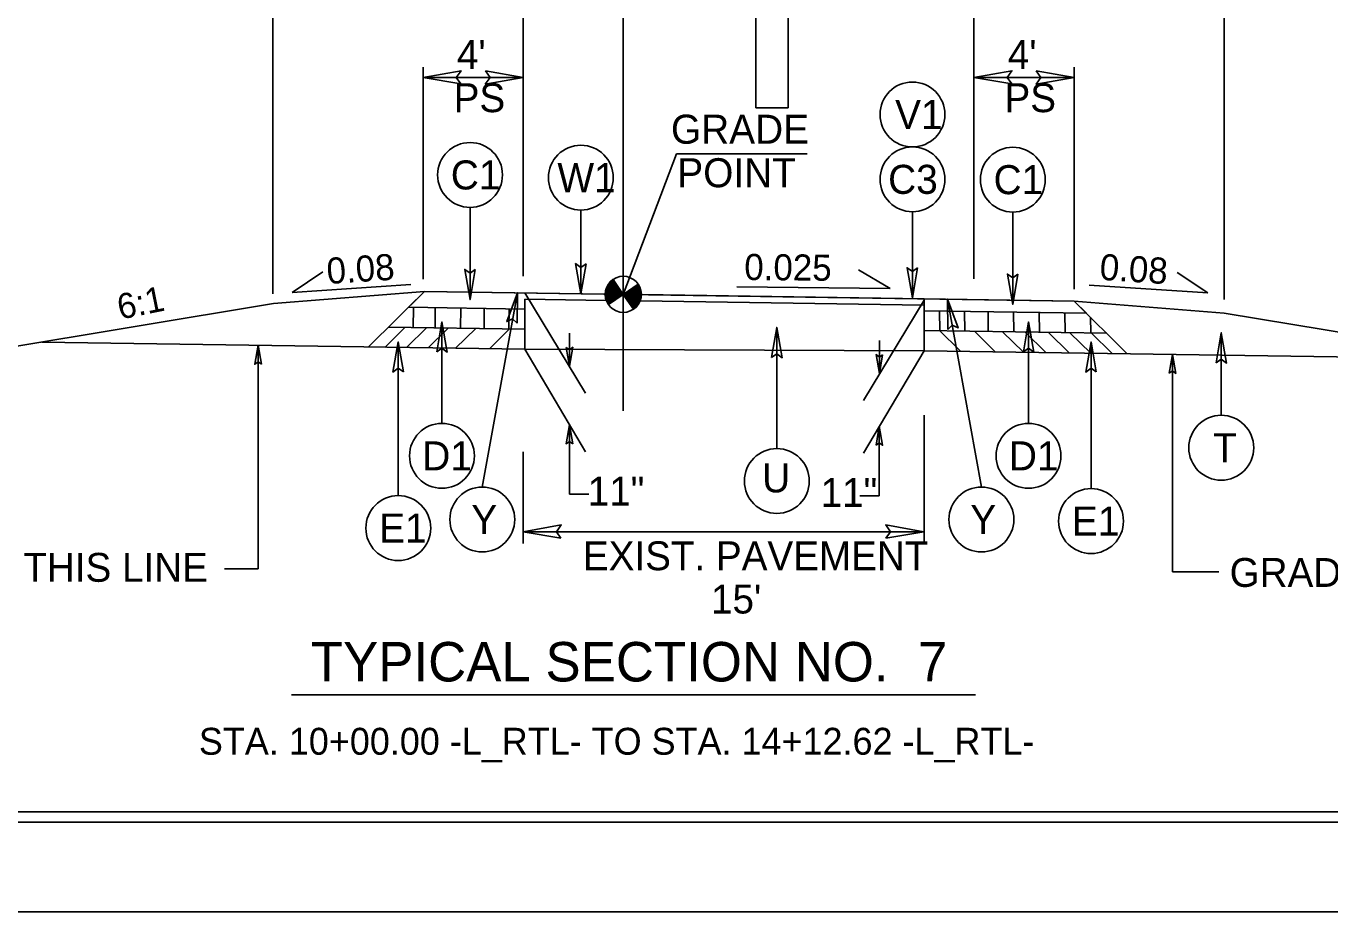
# Model space of a CAD drawing. Extents: x 2176156 to 2177167, y 76401 to 76644.
# Drawn here: x 2176797.7 to 2176849.7, y 76454.5 to 76489.9 of the extents above; entities that cross this region are included whole.
import ezdxf

# ---------------------------------------------------------------- set-up
doc = ezdxf.new("R2010")
doc.units = 0
for name, color, linetype in [('Exist Building', 7, 'Continuous'), ('Exist Building Metal Canopy', 7, 'Continuous'), ('Exist Roads Change in Surface', 7, 'Continuous'), ('Exist Roads Curbs', 7, 'Continuous'), ('Exist Roads EOP Other', 7, 'Continuous'), ('Exist Roads Soil', 7, 'Continuous'), ('Exist Structure Minor Culvert Topo', 7, 'Continuous'), ('Exist Structure Minor Drop Inlet', 7, 'Continuous'), ('Exist Utilities Other Pole CELL', 7, 'Continuous'), ('Exist Vegetation Woods Line', 7, 'Continuous'), ('Model Boundary Lines Text', 7, 'Continuous'), ('Old_Level_1', 7, 'Continuous'), ('Old_Level_3', 7, 'Continuous'), ('Prop North Arrow NAD83 for Plan Sheets CELL', 7, 'Continuous'), ('Sheet Cutting Line CELL', 7, 'Continuous'), ('Sheet Data Field CELL', 7, 'Continuous'), ('Sheet Plan CELL', 7, 'Continuous'), ('Sheet Plot Border Outside CELL', 7, 'Continuous'), ('Sheet Sticker Exception Certification CELL', 7, 'Continuous')]:
    doc.layers.add(name, color=color, linetype=linetype)

msp = doc.modelspace()

# ---------------------------------------------------------------- linework, layer by layer
at = {"layer": 'Exist Building'}
for p, q in [((2176817.578, 76476.959), (2176817.578, 76478.962)), ((2176833.533, 76476.902), (2176833.533, 76478.975)), ((2176817.578, 76476.959), (2176798.287, 76477.246)), ((2176856.606, 76476.559), (2176833.533, 76476.902))]:
    msp.add_line(p, q, dxfattribs=at)
at = {"layer": 'Exist Roads Change in Surface'}
for p, q in [((2176821.107, 76479.745), (2176821.519, 76479.153)), ((2176821.519, 76479.153), (2176822.11, 76479.565)), ((2176820.926, 76478.743), (2176821.519, 76479.153)), ((2176821.519, 76479.153), (2176820.926, 76478.743)), ((2176821.93, 76478.562), (2176821.519, 76479.153))]:
    msp.add_line(p, q, dxfattribs=at)
for points in [[(2176821.274, 76479.506), (2176820.798, 76479.174)], [(2176821.282, 76479.494), (2176820.798, 76479.157)], [(2176821.29, 76479.482), (2176820.798, 76479.14)], [(2176821.265, 76479.517), (2176820.799, 76479.193)], [(2176821.298, 76479.47), (2176820.799, 76479.122)], [(2176821.306, 76479.458), (2176820.799, 76479.105)], [(2176821.257, 76479.529), (2176820.8, 76479.211)], [(2176821.315, 76479.446), (2176820.801, 76479.089)], [(2176821.249, 76479.541), (2176820.802, 76479.23)], [(2176821.323, 76479.435), (2176820.802, 76479.072)], [(2176821.241, 76479.553), (2176820.804, 76479.249)], [(2176821.331, 76479.423), (2176820.804, 76479.056)], [(2176821.232, 76479.565), (2176820.806, 76479.268)], [(2176821.339, 76479.411), (2176820.807, 76479.04)], [(2176821.224, 76479.577), (2176820.81, 76479.288)], [(2176821.348, 76479.399), (2176820.81, 76479.025)], [(2176821.356, 76479.387), (2176820.813, 76479.009)], [(2176821.216, 76479.589), (2176820.815, 76479.309)], [(2176821.364, 76479.376), (2176820.816, 76478.994)], [(2176821.372, 76479.364), (2176820.819, 76478.978)], [(2176821.208, 76479.6), (2176820.82, 76479.33)], [(2176821.381, 76479.352), (2176820.823, 76478.964)], [(2176821.199, 76479.612), (2176820.826, 76479.352)], [(2176821.389, 76479.34), (2176820.827, 76478.949)], [(2176821.191, 76479.624), (2176820.832, 76479.374)], [(2176821.397, 76479.328), (2176820.832, 76478.935)], [(2176821.405, 76479.316), (2176820.837, 76478.921)], [(2176821.183, 76479.636), (2176820.84, 76479.397)], [(2176821.413, 76479.304), (2176820.842, 76478.906)], [(2176821.422, 76479.293), (2176820.847, 76478.893)], [(2176821.175, 76479.648), (2176820.849, 76479.421)], [(2176821.43, 76479.281), (2176820.853, 76478.879)], [(2176821.166, 76479.659), (2176820.859, 76479.445)], [(2176821.158, 76479.671), (2176820.872, 76479.472)], [(2176821.15, 76479.683), (2176820.886, 76479.499)], [(2176821.142, 76479.695), (2176820.902, 76479.528)], [(2176821.133, 76479.707), (2176820.922, 76479.56)], [(2176821.125, 76479.719), (2176820.949, 76479.596)], [(2176821.117, 76479.731), (2176820.983, 76479.637)], [(2176821.109, 76479.742), (2176821.044, 76479.697)], [(2176822.114, 76479.56), (2176822.114, 76479.56), (2176821.522, 76479.148)], [(2176822.122, 76479.548), (2176821.531, 76479.136)], [(2176822.129, 76479.535), (2176821.539, 76479.124)], [(2176822.137, 76479.523), (2176821.547, 76479.113)], [(2176822.144, 76479.511), (2176821.555, 76479.101)], [(2176822.151, 76479.498), (2176821.564, 76479.089)], [(2176822.158, 76479.485), (2176821.572, 76479.077)], [(2176822.165, 76479.472), (2176821.58, 76479.065)], [(2176822.172, 76479.46), (2176821.588, 76479.053)], [(2176822.178, 76479.446), (2176821.596, 76479.042)], [(2176822.183, 76479.432), (2176821.605, 76479.03)], [(2176822.189, 76479.419), (2176821.613, 76479.018)], [(2176822.194, 76479.405), (2176821.621, 76479.006)], [(2176822.199, 76479.39), (2176821.629, 76478.994)], [(2176822.204, 76479.377), (2176821.638, 76478.982)], [(2176822.209, 76479.362), (2176821.646, 76478.971)], [(2176822.213, 76479.348), (2176821.654, 76478.959)], [(2176822.217, 76479.333), (2176821.662, 76478.947)], [(2176822.22, 76479.318), (2176821.671, 76478.935)], [(2176822.223, 76479.302), (2176821.679, 76478.923)], [(2176822.226, 76479.286), (2176821.687, 76478.911)], [(2176821.438, 76479.269), (2176820.858, 76478.865)], [(2176821.446, 76479.257), (2176820.864, 76478.852)], [(2176821.455, 76479.245), (2176820.871, 76478.839)], [(2176821.463, 76479.234), (2176820.877, 76478.825)], [(2176821.471, 76479.222), (2176820.883, 76478.813)], [(2176821.479, 76479.21), (2176820.89, 76478.8)], [(2176821.488, 76479.198), (2176820.897, 76478.787)], [(2176821.496, 76479.186), (2176820.905, 76478.775)], [(2176821.504, 76479.174), (2176820.912, 76478.763)], [(2176821.512, 76479.162), (2176820.921, 76478.751), (2176820.921, 76478.751)], [(2176822.229, 76479.271), (2176821.695, 76478.9)], [(2176822.232, 76479.256), (2176821.704, 76478.888)], [(2176822.234, 76479.239), (2176821.712, 76478.876)], [(2176822.235, 76479.223), (2176821.72, 76478.864)], [(2176822.237, 76479.206), (2176821.728, 76478.852)], [(2176822.239, 76479.19), (2176821.736, 76478.84)], [(2176822.239, 76479.173), (2176821.745, 76478.829)], [(2176822.239, 76479.155), (2176821.753, 76478.817)], [(2176822.239, 76479.137), (2176821.761, 76478.805)], [(2176822.239, 76479.12), (2176821.769, 76478.793)], [(2176822.238, 76479.101), (2176821.778, 76478.781)], [(2176822.236, 76479.082), (2176821.786, 76478.769)], [(2176822.233, 76479.063), (2176821.794, 76478.758)], [(2176822.231, 76479.044), (2176821.802, 76478.746)], [(2176822.227, 76479.024), (2176821.811, 76478.734)], [(2176822.224, 76479.004), (2176821.819, 76478.722)], [(2176822.219, 76478.983), (2176821.827, 76478.71)], [(2176822.213, 76478.961), (2176821.835, 76478.698)], [(2176822.206, 76478.939), (2176821.844, 76478.687)], [(2176822.199, 76478.916), (2176821.852, 76478.675)], [(2176822.19, 76478.892), (2176821.86, 76478.663)], [(2176822.18, 76478.868), (2176821.868, 76478.651)], [(2176822.168, 76478.842), (2176821.876, 76478.639)], [(2176822.156, 76478.816), (2176821.885, 76478.627)], [(2176822.139, 76478.787), (2176821.893, 76478.616)], [(2176822.119, 76478.756), (2176821.901, 76478.604)], [(2176822.095, 76478.721), (2176821.909, 76478.592)], [(2176822.062, 76478.681), (2176821.918, 76478.58)], [(2176822.01, 76478.627), (2176821.926, 76478.568)]]:
    msp.add_lwpolyline(points, dxfattribs=at)
msp.add_circle((2176821.518, 76479.154), 0.721, dxfattribs=at)
for start, end in [(124.8249, 214.8249), (304.8249, 34.8249)]:
    msp.add_arc((2176821.518, 76479.154), 0.721, start, end, dxfattribs=at)
at = {"layer": 'Exist Roads EOP Other'}
for p, q in [((2176813.578, 76479.271), (2176807.542, 76478.788)), ((2176813.578, 76479.271), (2176812.937, 76478.635)), ((2176839.533, 76478.886), (2176813.578, 76479.271)), ((2176820.798, 76479.164), (2176813.578, 76479.271)), ((2176820.839, 76478.913), (2176817.578, 76478.962)), ((2176817.578, 76478.566), (2176817.578, 76478.962)), ((2176817.578, 76478.962), (2176820.839, 76478.913)), ((2176820.799, 76479.105), (2176820.799, 76479.105)), ((2176820.804, 76479.056), (2176820.804, 76479.056)), ((2176820.819, 76478.978), (2176820.819, 76478.979)), ((2176820.823, 76478.964), (2176820.823, 76478.964)), ((2176820.832, 76478.935), (2176820.832, 76478.935)), ((2176822.19, 76478.893), (2176833.533, 76478.725)), ((2176822.199, 76478.916), (2176822.199, 76478.916)), ((2176822.206, 76478.939), (2176822.206, 76478.939)), ((2176822.219, 76478.983), (2176822.219, 76478.983)), ((2176822.224, 76479.004), (2176822.223, 76479.004)), ((2176822.227, 76479.024), (2176822.227, 76479.024)), ((2176822.231, 76479.044), (2176822.231, 76479.044)), ((2176822.238, 76479.101), (2176822.237, 76479.101)), ((2176822.239, 76479.12), (2176822.238, 76479.119)), ((2176833.533, 76478.975), (2176822.239, 76479.143)), ((2176833.533, 76478.725), (2176833.533, 76478.975)), ((2176839.533, 76478.886), (2176833.533, 76478.975)), ((2176833.533, 76478.975), (2176833.533, 76478.496)), ((2176839.533, 76478.886), (2176845.519, 76478.407)), ((2176840.021, 76478.4), (2176839.533, 76478.886)), ((2176817.578, 76478.566), (2176812.937, 76478.635)), ((2176812.937, 76478.635), (2176817.578, 76478.566)), ((2176833.533, 76478.496), (2176840.021, 76478.4)), ((2176817.578, 76477.766), (2176812.145, 76477.846))]:
    msp.add_line(p, q, dxfattribs=at)
for points in [[(2176820.799, 76479.105), (2176820.799, 76479.105)], [(2176820.804, 76479.056), (2176820.804, 76479.056)], [(2176820.819, 76478.979), (2176820.819, 76478.978)], [(2176820.823, 76478.964), (2176820.823, 76478.964)], [(2176820.832, 76478.935), (2176820.832, 76478.935)], [(2176822.199, 76478.916), (2176822.199, 76478.916)], [(2176822.206, 76478.939), (2176822.206, 76478.939)], [(2176822.219, 76478.983), (2176822.219, 76478.983)], [(2176822.223, 76479.004), (2176822.224, 76479.004)], [(2176822.227, 76479.024), (2176822.227, 76479.024)], [(2176822.231, 76479.044), (2176822.231, 76479.044)], [(2176822.237, 76479.101), (2176822.238, 76479.101)], [(2176822.238, 76479.12), (2176822.239, 76479.12)]]:
    msp.add_lwpolyline(points, dxfattribs=at)
for start, end in [(179.2103, 182.5146), (182.5146, 183.8761), (183.8895, 185.2021), (185.2021, 187.8094), (187.8245, 189.0767), (189.0767, 194.0754), (194.0907, 195.2968), (195.2976, 196.5055), (196.5055, 197.7127), (197.7154, 199.5047), (338.7923, 340.731), (340.7368, 342.6429), (342.646, 344.4557), (344.4557, 346.2404), (346.2648, 347.9455), (347.9775, 349.598), (349.5984, 351.2038), (351.2196, 352.7539), (352.7539, 355.7778), (355.8127, 357.2394), (357.2652, 358.6425), (358.6425, 359.0871)]:
    msp.add_arc((2176821.518, 76479.154), 0.721, start, end, dxfattribs=at)
at = {"layer": 'Exist Roads Soil'}
for p, q in [((2176779.59, 76474.13), (2176807.542, 76478.788)), ((2176813.578, 76479.271), (2176811.346, 76477.052)), ((2176839.533, 76478.886), (2176841.649, 76476.781)), ((2176833.533, 76478.496), (2176840.021, 76478.4)), ((2176873.471, 76473.748), (2176845.519, 76478.407)), ((2176833.533, 76477.709), (2176840.826, 76477.6))]:
    msp.add_line(p, q, dxfattribs=at)
at = {"layer": 'Exist Structure Minor Drop Inlet'}
for p, q in [((2176826.817, 76486.605), (2176826.817, 76492.037)), ((2176828.098, 76492.037), (2176828.098, 76486.605)), ((2176828.098, 76486.605), (2176826.817, 76486.605))]:
    msp.add_line(p, q, dxfattribs=at)
at = {"layer": 'Exist Utilities Other Pole CELL'}
for p, q in [((2176808.291, 76479.233), (2176809.515, 76480.053)), ((2176832.184, 76479.388), (2176830.915, 76480.138)), ((2176844.872, 76479.213), (2176843.647, 76480.032)), ((2176808.291, 76479.233), (2176813.037, 76479.547)), ((2176832.184, 76479.388), (2176826.05, 76479.451)), ((2176844.872, 76479.213), (2176840.126, 76479.526))]:
    msp.add_line(p, q, dxfattribs=at)
at = {"layer": 'Model Boundary Lines Text'}
for p, q in [((2176813.122, 76477.819), (2176813.134, 76478.632)), ((2176813.997, 76477.819), (2176814.008, 76478.619)), ((2176815.014, 76477.804), (2176815.026, 76478.603)), ((2176815.954, 76477.79), (2176815.966, 76478.59)), ((2176816.951, 76477.775), (2176816.963, 76478.575)), ((2176834.159, 76477.702), (2176834.148, 76478.487)), ((2176835.157, 76477.678), (2176835.145, 76478.472)), ((2176836.097, 76477.671), (2176836.086, 76478.458)), ((2176837.115, 76477.655), (2176837.104, 76478.443)), ((2176838.143, 76477.64), (2176838.132, 76478.428)), ((2176839.166, 76477.625), (2176839.154, 76478.413)), ((2176840.194, 76477.609), (2176840.185, 76478.237)), ((2176811.986, 76477.029), (2176812.797, 76477.824)), ((2176812.861, 76477.029), (2176813.671, 76477.824)), ((2176813.722, 76477.017), (2176814.533, 76477.811)), ((2176814.821, 76477), (2176815.631, 76477.795)), ((2176816.167, 76476.98), (2176816.977, 76477.775)), ((2176834.968, 76476.899), (2176834.133, 76477.717)), ((2176836.377, 76476.858), (2176835.541, 76477.676)), ((2176837.507, 76476.843), (2176836.671, 76477.662)), ((2176838.395, 76476.83), (2176837.559, 76477.649)), ((2176839.333, 76476.816), (2176838.498, 76477.635)), ((2176840.19, 76476.803), (2176839.355, 76477.622)), ((2176841.047, 76476.79), (2176840.211, 76477.609)), ((2176808.269, 76463.157), (2176835.591, 76463.157))]:
    msp.add_line(p, q, dxfattribs=at)
at = {"layer": 'Old_Level_1'}
for points in [[(2176815.028, 76487.562), (2176813.519, 76487.822), (2176815.037, 76488.09), (2176814.844, 76487.822)], [(2176816.009, 76488.082), (2176817.519, 76487.822), (2176816.001, 76487.553), (2176816.194, 76487.822)], [(2176837.032, 76487.562), (2176835.523, 76487.822), (2176837.041, 76488.09), (2176836.848, 76487.822)], [(2176838.013, 76488.082), (2176839.523, 76487.822), (2176838.005, 76487.553), (2176838.197, 76487.822)], [(2176807.062, 76476.363), (2176806.932, 76477.118), (2176806.798, 76476.359), (2176806.932, 76476.455)], [(2176819.234, 76477.033), (2176819.366, 76476.279), (2176819.498, 76477.038), (2176819.364, 76476.941)], [(2176831.877, 76476.74), (2176831.745, 76475.985), (2176831.613, 76476.745), (2176831.747, 76476.648)], [(2176843.322, 76476), (2176843.452, 76476.755), (2176843.587, 76475.996), (2176843.452, 76476.092)], [(2176819.498, 76473.186), (2176819.366, 76473.94), (2176819.234, 76473.181), (2176819.368, 76473.277)], [(2176831.612, 76473.129), (2176831.744, 76473.883), (2176831.876, 76473.124), (2176831.742, 76473.221)], [(2176819.028, 76469.41), (2176817.519, 76469.67), (2176819.037, 76469.938), (2176818.844, 76469.67)], [(2176832.009, 76469.41), (2176833.519, 76469.67), (2176832.001, 76469.938), (2176832.194, 76469.67)]]:
    msp.add_lwpolyline(points, close=True, dxfattribs=at)
at = {"layer": 'Old_Level_3'}
for p, q in [((2176821.519, 76474.504), (2176821.519, 76498.995)), ((2176807.519, 76479.178), (2176807.519, 76495.92)), ((2176817.519, 76479.879), (2176817.519, 76495.92)), ((2176835.519, 76479.778), (2176835.519, 76495.92)), ((2176845.519, 76478.947), (2176845.519, 76495.67)), ((2176813.519, 76479.764), (2176813.519, 76488.226)), ((2176839.533, 76479.358), (2176839.533, 76488.226)), ((2176817.519, 76487.822), (2176813.519, 76487.822)), ((2176839.533, 76487.822), (2176835.519, 76487.822)), ((2176817.578, 76479.211), (2176820.003, 76475.203)), ((2176833.533, 76478.918), (2176831.108, 76474.91)), ((2176819.366, 76476.279), (2176819.366, 76477.607)), ((2176831.745, 76475.985), (2176831.745, 76477.313)), ((2176806.932, 76477.118), (2176806.932, 76468.191)), ((2176817.578, 76476.959), (2176820.003, 76472.865)), ((2176833.533, 76476.903), (2176831.107, 76472.808)), ((2176843.452, 76476.755), (2176843.452, 76468.068)), ((2176833.533, 76474.322), (2176833.533, 76469.201)), ((2176819.366, 76471.164), (2176819.366, 76473.94)), ((2176831.744, 76471.108), (2176831.744, 76473.883)), ((2176817.519, 76472.856), (2176817.519, 76469.201)), ((2176820.146, 76471.164), (2176819.366, 76471.164)), ((2176830.964, 76471.108), (2176831.744, 76471.108)), ((2176817.519, 76469.67), (2176833.519, 76469.67)), ((2176805.582, 76468.191), (2176806.932, 76468.191)), ((2176845.307, 76468.068), (2176843.452, 76468.068))]:
    msp.add_line(p, q, dxfattribs=at)
at = {"layer": 'Prop North Arrow NAD83 for Plan Sheets CELL'}
for p, q in [((2176823.643, 76484.769), (2176821.519, 76479.153)), ((2176828.861, 76484.769), (2176823.643, 76484.769)), ((2176815.396, 76482.629), (2176815.396, 76478.942)), ((2176819.823, 76482.52), (2176819.823, 76479.179)), ((2176833.068, 76482.453), (2176833.068, 76479.012)), ((2176837.077, 76482.441), (2176837.077, 76478.754)), ((2176815.885, 76471.453), (2176817.285, 76479.216)), ((2176835.822, 76471.453), (2176834.468, 76478.961)), ((2176814.274, 76473.997), (2176814.274, 76478.051)), ((2176827.65, 76472.99), (2176827.65, 76477.829)), ((2176837.705, 76473.997), (2176837.705, 76478.051)), ((2176812.53, 76471.11), (2176812.53, 76477.255)), ((2176840.201, 76471.389), (2176840.201, 76477.255)), ((2176845.403, 76474.32), (2176845.403, 76477.616))]:
    msp.add_line(p, q, dxfattribs=at)
for points in [[(2176820.03, 76480.379), (2176819.823, 76479.179), (2176819.61, 76480.385), (2176819.823, 76480.232)], [(2176815.603, 76480.142), (2176815.396, 76478.942), (2176815.183, 76480.149), (2176815.396, 76479.996)], [(2176833.275, 76480.212), (2176833.068, 76479.012), (2176832.855, 76480.219), (2176833.068, 76480.066)], [(2176837.283, 76479.954), (2176837.077, 76478.754), (2176836.863, 76479.961), (2176837.077, 76479.808)], [(2176817.276, 76477.999), (2176817.285, 76479.216), (2176816.861, 76478.067), (2176817.098, 76478.18)], [(2176834.478, 76477.743), (2176834.468, 76478.961), (2176834.892, 76477.811), (2176834.655, 76477.924)], [(2176814.067, 76476.851), (2176814.274, 76478.051), (2176814.487, 76476.845), (2176814.274, 76476.998)], [(2176827.444, 76476.629), (2176827.65, 76477.829), (2176827.864, 76476.622), (2176827.65, 76476.775)], [(2176837.499, 76476.851), (2176837.705, 76478.051), (2176837.919, 76476.845), (2176837.705, 76476.998)], [(2176812.736, 76476.055), (2176812.53, 76477.255), (2176812.316, 76476.048), (2176812.53, 76476.202)], [(2176840.408, 76476.055), (2176840.201, 76477.255), (2176839.988, 76476.048), (2176840.201, 76476.202)], [(2176845.197, 76476.416), (2176845.403, 76477.616), (2176845.617, 76476.409), (2176845.403, 76476.562)]]:
    msp.add_lwpolyline(points, close=True, dxfattribs=at)
for centre in [(2176833.068, 76486.341), (2176815.396, 76483.925), (2176819.823, 76483.816), (2176833.068, 76483.749), (2176837.077, 76483.737), (2176845.403, 76473.024), (2176814.274, 76472.701), (2176837.705, 76472.701), (2176827.651, 76471.694), (2176812.53, 76469.814), (2176815.885, 76470.157), (2176835.822, 76470.157), (2176840.201, 76470.093)]:
    msp.add_circle(centre, 1.296, dxfattribs=at)
at = {"layer": 'Sheet Cutting Line CELL'}
msp.add_lwpolyline([(2176898.707, 76630.475), (2176629.267, 76630.475), (2176629.267, 76454.475), (2176898.707, 76454.475)], close=True, dxfattribs=at)
at = {"layer": 'Sheet Data Field CELL'}
msp.add_lwpolyline([(2176895.987, 76626.475), (2176655.987, 76626.475), (2176655.987, 76458.475), (2176895.987, 76458.475)], close=True, dxfattribs=at)
at = {"layer": 'Sheet Plan CELL'}
msp.add_line((2176833.533, 76476.903), (2176817.578, 76476.959), dxfattribs=at)
at = {"layer": 'Sheet Plot Border Outside CELL'}
msp.add_lwpolyline([(2176897.987, 76626.883), (2176631.347, 76626.883), (2176631.347, 76458.067), (2176897.987, 76458.067)], close=True, dxfattribs=at)
at = {"layer": 'Sheet Sticker Exception Certification CELL'}
msp.add_line((2176629.267, 76454.475), (2176898.707, 76454.475), dxfattribs=at)

# ---------------------------------------------------------------- texts
at = {"layer": 'Exist Building Metal Canopy'}
msp.add_text('TYPICAL SECTION NO.  7', height=1.5766, rotation=0, dxfattribs=at).set_placement((2176809.035, 76463.685))
at = {"layer": 'Exist Roads Curbs'}
msp.add_text('6:1', height=1.0064, rotation=11.4865, dxfattribs=at).set_placement((2176801.417, 76478.142))
at = {"layer": 'Exist Structure Minor Culvert Topo'}
for s, height, p in [("4' ", 1.1533, (2176814.871, 76488.163)), ("4' ", 1.1533, (2176836.875, 76488.163)), ('PS', 1.1533, (2176814.742, 76486.433)), ('PS', 1.1533, (2176836.745, 76486.433)), ('EXIST. PAVEMENT ', 1.15334, (2176819.905, 76468.13)), ('GRADE TO THIS LINE', 1.15334, (2176789.07, 76467.668)), ('GRADE TO THIS LINE', 1.15334, (2176845.738, 76467.464)), ("15'", 1.1533, (2176825.021, 76466.4))]:
    msp.add_text(s, height=height, dxfattribs=at).set_placement(p)
at = {"layer": 'Exist Utilities Other Pole CELL'}
for s, rotation, p in [('0.08', 3.7801, (2176809.701, 76479.563)), ('0.025', 359.4073, (2176826.346, 76479.729)), ('0.08', 356.2199, (2176840.522, 76479.737))]:
    msp.add_text(s, height=1.0429, rotation=rotation, dxfattribs=at).set_placement(p)
at = {"layer": 'Exist Vegetation Woods Line'}
msp.add_text('STA. 10+00.00 -L_RTL- TO STA. 14+12.62 -L_RTL-', height=1.0742, dxfattribs=at).set_placement((2176804.565, 76460.758))
at = {"layer": 'Prop North Arrow NAD83 for Plan Sheets CELL'}
for s, rotation, p in [('V1', 0.0003, (2176832.375, 76485.761)), ('GRADE', 0.0002, (2176823.421, 76485.173)), ('C1', 0.0003, (2176814.627, 76483.345)), ('POINT', 0.0002, (2176823.674, 76483.433)), ('W1', 0.0003, (2176818.886, 76483.236)), ('C3', 0.0003, (2176832.096, 76483.169)), ('C1', 0.0003, (2176836.308, 76483.157)), ('T', 0.0003, (2176845.077, 76472.444)), ('D1', 0.0003, (2176813.488, 76472.121)), ('D1', 0.0003, (2176836.92, 76472.121)), ('U', 0.0003, (2176827.064, 76471.24)), ('Y', 359.9997, (2176815.446, 76469.577)), ('Y', 0.0003, (2176835.377, 76469.577)), ('E1', 359.9997, (2176839.437, 76469.513)), ('E1', 359.9997, (2176811.766, 76469.234))]:
    msp.add_text(s, height=1.16, rotation=rotation, dxfattribs=at).set_placement(p)
for p in [(2176820.098, 76470.714), (2176829.399, 76470.658)]:
    msp.add_text('11"', height=1.1533, dxfattribs=at).set_placement(p)

doc.saveas('drawing.dxf')
